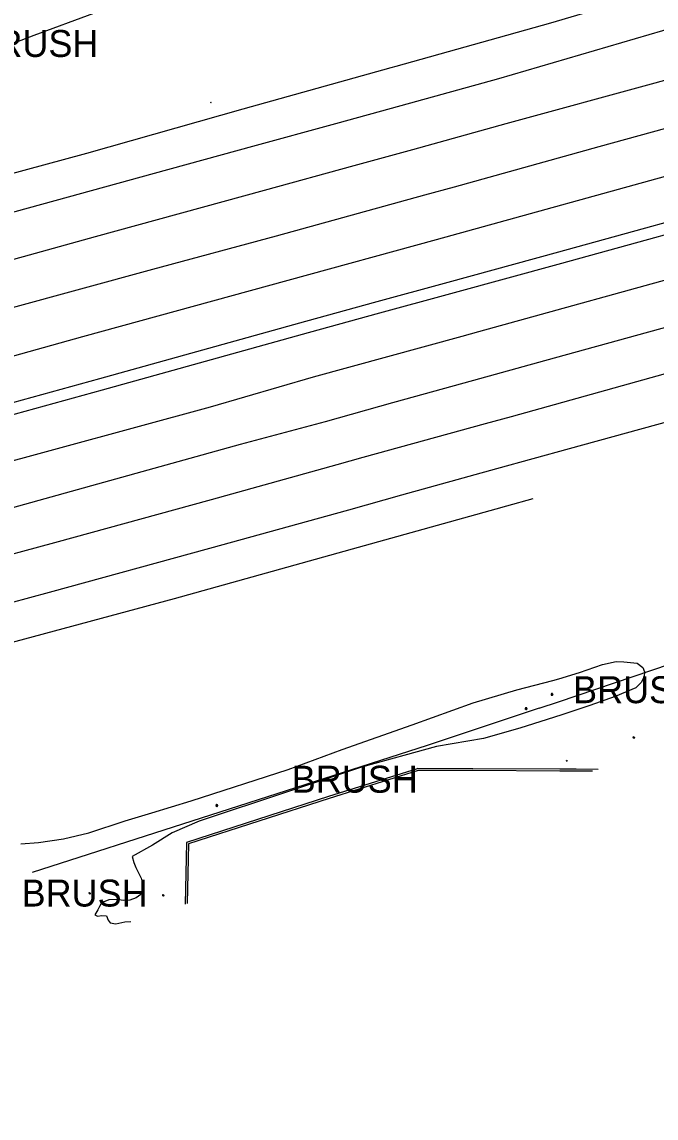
# Model space of a CAD drawing. Extents: x 2129547 to 2134906, y 657330 to 659734.
# Drawn here: x 2130233.3 to 2130398.1, y 657723.2 to 658008.1 of the extents above; entities that cross this region are included whole.
import ezdxf

# ---------------------------------------------------------------- set-up
doc = ezdxf.new("R2010")
doc.units = 0
for name, color, linetype in [('LT_X_Poles', 7, 'Continuous'), ('PM_X_Edge_Line', 7, 'Continuous'), ('PM_X_Lane_Line', 7, 'Continuous'), ('PV_X_Curb', 7, 'Continuous'), ('PV_X_EOP2', 7, 'Continuous'), ('PV_X_Parking_Lot', 7, 'Continuous'), ('PV_X_Shoulder', 7, 'Continuous'), ('RD_X_Cells', 7, 'Continuous'), ('RD_X_Concrete_Barrier', 7, 'Continuous'), ('RD_X_Fence', 7, 'Continuous'), ('VG_X_Cells', 7, 'Continuous'), ('VG_X_Shrub_Line_Lt', 7, 'Continuous'), ('VG_X_Text', 7, 'Continuous')]:
    doc.layers.add(name, color=color, linetype=linetype)

msp = doc.modelspace()

# ---------------------------------------------------------------- linework, layer by layer
at = {"layer": 'LT_X_Poles'}
msp.add_lwpolyline([(2130374.96, 657816.24), (2130374.88, 657815.94), (2130375, 657815.94)], dxfattribs=at)
msp.add_circle((2130374.92, 657816.09), 0.065, dxfattribs=at)
at = {"layer": 'PM_X_Edge_Line'}
for points in [[(2129783, 657797.65), (2129820.8, 657807.78), (2129922.27, 657836.17), (2129994.45, 657856.25), (2130028.21, 657865.49), (2130093.84, 657883.42), (2130153.98, 657899.99), (2130199.12, 657912.39), (2130249.09, 657926.31), (2130302.49, 657941.01), (2130341.07, 657951.58), (2130345.17, 657952.7), (2130404.65, 657969.17), (2130458.77, 657984.04), (2130511.95, 657998.61), (2130564.35, 658012.89), (2130611.28, 658025.79), (2130665.46, 658040.53), (2130717.36, 658054.84), (2130762.68, 658067.32), (2130806.63, 658079.2), (2130851.4, 658091.68), (2130882.88, 658100.31), (2130891, 658102.57)], [(2129782.31, 657770.56), (2129838.02, 657785.8), (2129918.94, 657807.73), (2130006.57, 657832.43), (2130060.5, 657847.21), (2130112.38, 657861.87), (2130166.66, 657876.43), (2130223.01, 657891.92), (2130282.32, 657908.07), (2130309.12, 657915.87), (2130347.7, 657926.43), (2130352.07, 657927.63), (2130411.57, 657944.11), (2130465.65, 657958.97), (2130518.8, 657973.53), (2130571.22, 657987.81), (2130618.14, 658000.71), (2130672.33, 658015.45), (2130724.27, 658029.78), (2130769.53, 658042.24), (2130813.51, 658054.13), (2130850.23, 658064.39), (2130880.11, 658072.6), (2130898.43, 658077.6)], [(2129783.9, 657836.03), (2129845.86, 657853.1), (2129914.14, 657872.06), (2129982.95, 657891.18), (2130034.97, 657905.36), (2130096.22, 657921.98), (2130157.01, 657938.72), (2130212.56, 657953.66), (2130267.72, 657968.86), (2130293.3, 657975.86), (2130314.89, 657981.71), (2130331.88, 657986.43), (2130357.23, 657993.47), (2130407.01, 658008.01), (2130461.65, 658024.51), (2130507.73, 658038.43), (2130546.43, 658050.14)], [(2129781.33, 657733.06), (2129822.4, 657744.28), (2129902.75, 657766.7), (2130016.9, 657798.42), (2130084.9, 657816.89), (2130135.24, 657830.94), (2130189.26, 657846.05), (2130240.42, 657859.85), (2130282.16, 657871.36), (2130318.23, 657881.32), (2130332.01, 657885.16), (2130356.78, 657892.02), (2130375.64, 657897.24), (2130413.2, 657907.59), (2130448.12, 657917.07), (2130481.79, 657926.44), (2130514.96, 657935.23), (2130533.56, 657939.51)]]:
    msp.add_lwpolyline(points, dxfattribs=at)
at = {"layer": 'PM_X_Lane_Line'}
for points in [[(2129783.61, 657823.91), (2129810.31, 657831.3), (2129849.13, 657842.04), (2129899.17, 657855.99), (2129939.24, 657867.08), (2129976.77, 657877.74), (2130017.08, 657888.49), (2130055.92, 657899.02), (2130096.18, 657909.94), (2130136.01, 657920.82), (2130175.79, 657931.24), (2130213.92, 657941.68), (2130252.44, 657952.34), (2130296.32, 657964.4), (2130319.63, 657970.79), (2130334.89, 657975.01), (2130359.14, 657981.71), (2130397.93, 657992.31), (2130437.8, 658003.41), (2130477.78, 658014.39), (2130517.26, 658025.11), (2130555.6, 658035.62)], [(2129783.29, 657810.14), (2129804.42, 657815.9), (2129840.99, 657826.02), (2129880.02, 657836.71), (2129920.48, 657848.01), (2129956.91, 657858.04), (2129996.24, 657869.42), (2130036.61, 657880.37), (2130073.22, 657890.36), (2130113.36, 657901.36), (2130150.86, 657911.7), (2130189.83, 657922.56), (2130229.83, 657933.62), (2130267.33, 657943.86), (2130299.45, 657952.54), (2130338.02, 657963.15), (2130345.77, 657965.28), (2130383.32, 657975.73), (2130422.46, 657986.54), (2130460.74, 657996.93), (2130499.23, 658007.56), (2130538.61, 658018.28)], [(2129781.97, 657758.13), (2129790.58, 657760.5), (2129829.56, 657771.14), (2129869.63, 657781.89), (2129945.41, 657803.63), (2129982.9, 657813.16), (2130010.71, 657821.32), (2130048.97, 657831.8), (2130087.83, 657842.51), (2130137.07, 657856.3), (2130176.24, 657866.81), (2130213.39, 657877.02), (2130252.97, 657888.01), (2130290.12, 657898.33), (2130312.18, 657904.29), (2130329.72, 657909.17), (2130350.72, 657914.99), (2130369.2, 657920.1), (2130409.79, 657931.31), (2130447.91, 657941.44), (2130484.91, 657951.63), (2130526.03, 657962.85), (2130563.47, 657973.17)], [(2130557.28, 657959.92), (2130518.18, 657949.28), (2130479.22, 657938.42), (2130439.87, 657927.68), (2130400.48, 657916.61), (2130360.47, 657905.46), (2130353.72, 657903.61), (2130321.86, 657894.87), (2130315.15, 657893.02), (2130282.49, 657883.85), (2130241.71, 657872.68), (2130201.93, 657862), (2130163.85, 657851.39), (2130126, 657840.99), (2130086.64, 657830.21), (2130048.06, 657819.28), (2130006.64, 657808.18), (2129969.33, 657798.07), (2129930.34, 657787.23), (2129890.21, 657775.75), (2129850.72, 657764.54), (2129813.2, 657754.11), (2129781.62, 657745.43)]]:
    msp.add_lwpolyline(points, dxfattribs=at)
at = {"layer": 'PV_X_Curb'}
msp.add_lwpolyline([(2130383.09, 657813.82), (2130377.39, 657813.84), (2130373.11, 657813.86), (2130350.54, 657813.98), (2130336.22, 657814), (2130336, 657813.93), (2130313, 657806.74), (2130276.06, 657794.83), (2130275.74, 657778.79)], dxfattribs=at)
at = {"layer": 'PV_X_EOP2'}
for points in [[(2129783, 657797.65), (2129820.8, 657807.78), (2129922.27, 657836.17), (2129994.45, 657856.25), (2130028.21, 657865.49), (2130093.84, 657883.42), (2130153.98, 657899.99), (2130199.12, 657912.39), (2130249.09, 657926.31), (2130302.49, 657941.01), (2130341.07, 657951.58), (2130345.17, 657952.7), (2130404.65, 657969.17), (2130458.77, 657984.04), (2130511.95, 657998.61), (2130564.35, 658012.89), (2130611.28, 658025.79), (2130665.46, 658040.53), (2130717.36, 658054.84), (2130762.68, 658067.32), (2130806.63, 658079.2), (2130851.4, 658091.68), (2130882.88, 658100.31), (2130891, 658102.57)], [(2129782.31, 657770.56), (2129838.02, 657785.8), (2129918.94, 657807.73), (2130006.57, 657832.43), (2130060.5, 657847.21), (2130112.38, 657861.87), (2130166.66, 657876.43), (2130223.01, 657891.92), (2130282.32, 657908.07), (2130309.12, 657915.87), (2130347.7, 657926.43), (2130352.07, 657927.63), (2130411.57, 657944.11), (2130465.65, 657958.97), (2130518.8, 657973.53), (2130571.22, 657987.81), (2130618.14, 658000.71), (2130672.33, 658015.45), (2130724.27, 658029.78), (2130769.53, 658042.24), (2130813.51, 658054.13), (2130850.23, 658064.39), (2130880.11, 658072.6), (2130898.43, 658077.6)], [(2129783.9, 657836.03), (2129845.86, 657853.1), (2129914.14, 657872.06), (2129982.95, 657891.18), (2130034.97, 657905.36), (2130096.22, 657921.98), (2130157.01, 657938.72), (2130212.56, 657953.66), (2130267.72, 657968.86), (2130293.3, 657975.86), (2130314.89, 657981.71), (2130331.88, 657986.43), (2130357.23, 657993.47), (2130407.01, 658008.01), (2130461.65, 658024.51), (2130507.73, 658038.43), (2130546.43, 658050.14)], [(2129781.33, 657733.06), (2129822.4, 657744.28), (2129902.75, 657766.7), (2130016.9, 657798.42), (2130084.9, 657816.89), (2130135.24, 657830.94), (2130189.26, 657846.05), (2130240.42, 657859.85), (2130282.16, 657871.36), (2130318.23, 657881.32), (2130332.01, 657885.16), (2130356.78, 657892.02), (2130375.64, 657897.24), (2130413.2, 657907.59), (2130448.12, 657917.07), (2130481.79, 657926.44), (2130514.96, 657935.23), (2130533.56, 657939.51)]]:
    msp.add_lwpolyline(points, dxfattribs=at)
at = {"layer": 'PV_X_Parking_Lot'}
msp.add_lwpolyline([(2130381.59, 657813.32), (2130377.53, 657813.34), (2130373.11, 657813.36), (2130350.54, 657813.48), (2130336.3, 657813.5), (2130313.15, 657806.27), (2130276.55, 657794.46), (2130276.24, 657778.95)], dxfattribs=at)
at = {"layer": 'PV_X_Shoulder'}
for points in [[(2129784.13, 657845.78), (2129820.77, 657855.85), (2129911.85, 657881.4), (2129982.97, 657901.46), (2130035.32, 657915.88), (2130072.23, 657925.85), (2130123.9, 657939.97), (2130169.63, 657952.07), (2130213.34, 657964.08), (2130250.16, 657974.02), (2130290.75, 657985.53), (2130329.29, 657996.26), (2130330.56, 657996.61), (2130370.76, 658007.9), (2130412.81, 658020.38), (2130453.6, 658032.45), (2130494.01, 658044.69), (2130534.58, 658056.98)], [(2129781.12, 657723.15), (2129791.26, 657725.96), (2129847.2, 657740.42), (2129910.54, 657757.22), (2129956.62, 657769.85), (2130017.82, 657787.52), (2130067.36, 657801.54), (2130112.53, 657814.1), (2130168.41, 657829.75), (2130217.23, 657843.2), (2130272.91, 657858.21), (2130320.81, 657871.55), (2130356.56, 657881.59), (2130359.33, 657882.35), (2130366.22, 657884.23)]]:
    msp.add_lwpolyline(points, dxfattribs=at)
at = {"layer": 'RD_X_Cells'}
msp.add_lwpolyline([(2130282.34, 657987.15), (2130282.41, 657987.11), (2130282.47, 657987.15), (2130282.47, 657987.22), (2130282.41, 657987.26), (2130282.34, 657987.22), (2130282.34, 657987.15)], dxfattribs=at)
at = {"layer": 'RD_X_Concrete_Barrier'}
for points in [[(2130565.99, 658001.27), (2130519.98, 657988.71), (2130477.65, 657977.23), (2130423.68, 657962.34), (2130372.81, 657948.31), (2130344.01, 657940.43), (2130324.59, 657935.12), (2130305.44, 657929.81), (2130253.45, 657915.37), (2130203.07, 657901.49), (2130144.32, 657885.41), (2130086.58, 657869.4), (2130031.8, 657854.67), (2129999.77, 657845.79), (2129936.01, 657828.01), (2129863.42, 657807.87), (2129795.91, 657789.82), (2129782.73, 657786.14)], [(2129782.65, 657783), (2129796.7, 657786.92), (2129864.21, 657804.98), (2129936.81, 657825.12), (2130000.57, 657842.9), (2130032.59, 657851.78), (2130087.37, 657866.51), (2130145.12, 657882.52), (2130203.86, 657898.59), (2130254.25, 657912.48), (2130306.25, 657926.92), (2130325.39, 657932.23), (2130344.78, 657937.53), (2130373.6, 657945.42), (2130424.48, 657959.44), (2130478.44, 657974.34), (2130520.77, 657985.82), (2130566.78, 657998.38)]]:
    msp.add_lwpolyline(points, dxfattribs=at)
at = {"layer": 'RD_X_Fence'}
msp.add_line((2130367.77, 657829.71), (2130372.76, 657831.4), dxfattribs=at)
for points in [[(2130372.76, 657831.4), (2130401.89, 657841.24), (2130444.91, 657852.66), (2130493.65, 657863.34), (2130547.6, 657875.39), (2130589.68, 657885.4), (2130636.62, 657895.64), (2130749.57, 657921.43), (2130795.47, 657932.48), (2130846.52, 657944.86), (2130897.31, 657956.97), (2130898.55, 657989.46), (2130902.91, 657992.37), (2130925.34, 657969.73), (2130931.96, 657970.88)], [(2130367.77, 657829.71), (2130338.65, 657820.06), (2130277.46, 657800.37), (2130235.9, 657786.99)]]:
    msp.add_lwpolyline(points, dxfattribs=at)
at = {"layer": 'VG_X_Cells'}
for p, q in [((2130392.11, 657822.12), (2130392.36, 657822.12)), ((2130392.36, 657822.12), (2130392.14, 657822.18)), ((2130392.36, 657822.12), (2130392.14, 657822.05)), ((2130392.36, 657822.12), (2130392.16, 657822.24)), ((2130392.36, 657822.12), (2130392.16, 657822.01)), ((2130392.36, 657822.12), (2130392.16, 657821.97)), ((2130392.36, 657822.12), (2130392.18, 657822.3)), ((2130392.36, 657822.12), (2130392.21, 657821.95)), ((2130392.36, 657822.12), (2130392.24, 657821.92)), ((2130392.36, 657822.12), (2130392.27, 657821.91)), ((2130392.36, 657822.12), (2130392.29, 657821.88)), ((2130392.36, 657822.12), (2130392.3, 657822.35)), ((2130392.36, 657822.12), (2130392.33, 657821.89)), ((2130392.36, 657822.12), (2130392.42, 657822.36)), ((2130392.36, 657822.12), (2130392.49, 657822.32)), ((2130392.36, 657822.12), (2130392.54, 657822.26)), ((2130392.36, 657822.12), (2130392.59, 657822.2)), ((2130392.36, 657822.12), (2130392.58, 657822.13)), ((2130392.36, 657821.86), (2130392.36, 657822.12)), ((2130392.36, 657822.12), (2130392.4, 657821.89)), ((2130392.36, 657822.12), (2130392.45, 657821.89)), ((2130392.36, 657822.12), (2130392.48, 657821.93)), ((2130392.36, 657822.12), (2130392.54, 657821.95)), ((2130392.36, 657822.12), (2130392.55, 657822)), ((2130392.36, 657822.12), (2130392.58, 657822.03)), ((2130392.36, 657822.12), (2130392.6, 657822.08)), ((2130250.9, 657781.61), (2130250.7, 657781.72)), ((2130250.9, 657781.61), (2130250.72, 657781.78)), ((2130250.9, 657781.61), (2130250.84, 657781.84)), ((2130250.9, 657781.61), (2130250.96, 657781.84)), ((2130250.9, 657781.61), (2130251.03, 657781.8)), ((2130250.9, 657781.61), (2130251.08, 657781.75)), ((2130250.65, 657781.61), (2130250.9, 657781.61)), ((2130250.9, 657781.61), (2130250.68, 657781.66)), ((2130250.9, 657781.61), (2130250.68, 657781.53)), ((2130250.9, 657781.61), (2130250.7, 657781.49)), ((2130250.9, 657781.61), (2130250.7, 657781.46)), ((2130250.9, 657781.61), (2130250.75, 657781.43)), ((2130250.9, 657781.61), (2130250.78, 657781.4)), ((2130250.9, 657781.61), (2130250.81, 657781.39)), ((2130250.9, 657781.61), (2130250.83, 657781.36)), ((2130250.9, 657781.61), (2130250.87, 657781.38)), ((2130250.9, 657781.61), (2130251.13, 657781.69)), ((2130250.9, 657781.34), (2130250.9, 657781.61)), ((2130250.9, 657781.61), (2130250.94, 657781.37)), ((2130250.9, 657781.61), (2130250.99, 657781.37)), ((2130250.9, 657781.61), (2130251.02, 657781.42)), ((2130250.9, 657781.61), (2130251.08, 657781.43)), ((2130250.9, 657781.61), (2130251.09, 657781.48)), ((2130250.9, 657781.61), (2130251.12, 657781.51)), ((2130250.9, 657781.61), (2130251.14, 657781.56)), ((2130250.9, 657781.61), (2130251.12, 657781.61)), ((2130269.77, 657781.08), (2130270.02, 657781.08)), ((2130270.02, 657781.08), (2130269.8, 657781.13)), ((2130270.02, 657781.08), (2130269.81, 657781)), ((2130270.02, 657781.08), (2130269.82, 657780.96)), ((2130270.02, 657781.08), (2130269.83, 657781.19)), ((2130270.02, 657781.08), (2130269.83, 657780.93)), ((2130270.02, 657781.08), (2130269.85, 657781.25)), ((2130270.02, 657781.08), (2130269.87, 657780.9)), ((2130270.02, 657781.08), (2130269.91, 657780.87)), ((2130270.02, 657781.08), (2130269.94, 657780.86)), ((2130270.02, 657781.08), (2130269.96, 657781.31)), ((2130270.02, 657781.08), (2130269.96, 657780.83)), ((2130270.02, 657781.08), (2130269.99, 657780.85)), ((2130270.02, 657781.08), (2130270.08, 657781.31)), ((2130270.02, 657781.08), (2130270.15, 657781.27)), ((2130270.02, 657781.08), (2130270.2, 657781.22)), ((2130270.02, 657781.08), (2130270.26, 657781.16)), ((2130270.02, 657780.81), (2130270.02, 657781.08)), ((2130270.02, 657781.08), (2130270.07, 657780.84)), ((2130270.02, 657781.08), (2130270.12, 657780.84)), ((2130270.02, 657781.08), (2130270.15, 657780.89)), ((2130270.02, 657781.08), (2130270.2, 657780.9)), ((2130270.02, 657781.08), (2130270.21, 657780.95)), ((2130270.02, 657781.08), (2130270.24, 657780.98)), ((2130270.02, 657781.08), (2130270.26, 657781.03)), ((2130270.02, 657781.08), (2130270.25, 657781.08))]:
    msp.add_line(p, q, dxfattribs=at)
for centre in [(2130371.08, 657833.31), (2130364.35, 657829.59), (2130283.94, 657804.42)]:
    msp.add_circle(centre, 0.012, dxfattribs=at)
for centre, radius, start, end in [((2130370.92, 657833.4), 0.0735, 39.0625, 279.5412), ((2130370.94, 657833.23), 0.0987, 96.1722, 320.5737), ((2130371.03, 657833.48), 0.0658, 354.0047, 205.9741), ((2130371.13, 657833.18), 0.114, 184.9476, 19.4572), ((2130371.17, 657833.45), 0.0776, 323.83, 165.0376), ((2130371.25, 657833.31), 0.0957, 259.1453, 101.4596), ((2130364.18, 657829.68), 0.0735, 39.0625, 279.5412), ((2130364.21, 657829.51), 0.0987, 96.1722, 320.5737), ((2130364.3, 657829.76), 0.0658, 354.0047, 205.9741), ((2130364.4, 657829.46), 0.114, 184.9476, 19.4572), ((2130364.44, 657829.73), 0.0776, 323.83, 165.0376), ((2130364.52, 657829.59), 0.0957, 259.1453, 101.4596), ((2130283.77, 657804.52), 0.0735, 39.0625, 279.5412), ((2130283.89, 657804.59), 0.0658, 354.0047, 205.9741), ((2130284.03, 657804.56), 0.0776, 323.83, 165.0376), ((2130284.11, 657804.42), 0.0957, 259.1453, 101.4596), ((2130283.79, 657804.34), 0.0987, 96.1722, 320.5737), ((2130283.98, 657804.29), 0.114, 184.9476, 19.4572)]:
    msp.add_arc(centre, radius, start, end, dxfattribs=at)
at = {"layer": 'VG_X_Shrub_Line_Lt'}
for points in [[(2130265.59, 658014.49), (2130251.84, 658010.32), (2130236.4, 658004.62), (2130220.27, 657998.48), (2130215.14, 657996.5), (2130211.21, 657995), (2130209.68, 657994.58), (2130208.73, 657994.71), (2130208.58, 657995.44), (2130210.79, 658001.16), (2130214.98, 658010.69)], [(2130371.31, 657836.91), (2130372.89, 657837.33), (2130378.24, 657838.99), (2130384.19, 657841.04), (2130387.77, 657841.89), (2130389.8, 657841.79), (2130393.21, 657841.44), (2130394.72, 657840.27), (2130395.16, 657839.2), (2130395.04, 657837.93), (2130394.35, 657836.49), (2130392.87, 657835), (2130387.47, 657832.76), (2130380.94, 657830.44), (2130373.65, 657828.03)], [(2130233.02, 657794.45), (2130237.59, 657794.84), (2130244.04, 657795.77), (2130250.68, 657797.33), (2130260.12, 657800.43), (2130267.05, 657802.53), (2130277.25, 657805.61), (2130302.51, 657813.77), (2130316.5, 657819.02), (2130334.74, 657825.39), (2130350.61, 657831.12), (2130361.98, 657834.47), (2130371.31, 657836.91)], [(2130373.65, 657828.03), (2130369.87, 657826.78), (2130362.76, 657824.52), (2130353.24, 657821.85), (2130341.06, 657819.78), (2130321.54, 657814.42), (2130302.57, 657808.05), (2130279.39, 657800.37), (2130272.37, 657797.3), (2130267.2, 657794.13), (2130261.9, 657791.15), (2130262.39, 657789.6), (2130262.9, 657788.29), (2130263.64, 657786.78), (2130264.24, 657785.52), (2130264.6, 657784.1), (2130264.66, 657782.44), (2130264.19, 657781.27), (2130262.97, 657780.42), (2130261.35, 657779.8), (2130259.56, 657779.7), (2130258.07, 657779.96), (2130255.85, 657779.88), (2130253.98, 657779.14), (2130253.47, 657778.16), (2130252.97, 657777.25), (2130252.2, 657775.97), (2130252.88, 657775.66), (2130254.04, 657775.78), (2130255.26, 657775.7), (2130255.72, 657774.57), (2130256.17, 657773.93), (2130257.66, 657773.61), (2130260.06, 657774.15), (2130261.55, 657774.25)]]:
    msp.add_lwpolyline(points, dxfattribs=at)

# ---------------------------------------------------------------- texts
at = {"layer": 'VG_X_Text'}
for p in [(2130220.39, 657999.03), (2130376.56, 657831.02), (2130303.42, 657807.75), (2130233.18, 657778.15)]:
    msp.add_text('BRUSH', height=7, dxfattribs=at).set_placement(p)

doc.saveas('drawing.dxf')
